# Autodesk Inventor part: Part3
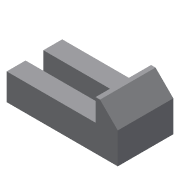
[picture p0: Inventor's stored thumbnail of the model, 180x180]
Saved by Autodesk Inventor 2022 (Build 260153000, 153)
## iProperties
Created: 2002-01
Part Number: Part3
Document SubType Name: Modeling
Designer: ***
Density: 1 g/cm^3
Material: Generic
Appearance: Default
Control State: 0
Master: False
Checked Out: False
Shininess: 77.0
Length Units: 11269
Angle Units: 11279
Time Units: 11290
Mass Units: 11283
Length Display Precision: 3
Angle Display Precision: 2
Density: 0.0
Volumn: 0.0
Area: 0.0
PropertySet Name: Model Information
Author: ***
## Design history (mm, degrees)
sketch "Sketch2"
  geometry: L1 (23.289, -5.477)-(-16.711, -5.477); L2 (-16.711, -5.477)-(-16.711, 4.523); L3 (-16.711, 4.523)-(-18.711, 4.523); L4 (-18.711, 4.523)-(-26.711, -3.477); L5 (-26.711, -3.477)-(-26.711, -17.477); L6 (-26.711, -17.477)-(23.289, -17.477); L7 (23.289, -17.477)-(23.289, -5.477)
  constraints: 14 end point, 4 parallel, 1 horizontal, 1 perpendicular
  dimensions: "d0" = 50 distance of L5.end L6.end; "d1" = 12 distance of L6.end L1.start; "d2" = 22 distance between parallel lines of L3 L6; "d3" = 135 deg angle of L5 L4; "d4" = 2 distance of L2.end L3.end; "d5" = 40 distance of L1.start L1.end
extrude "Extrusion1" new body sketch "Sketch2" stored distance "d6" = 25; taper "d7" = 0 deg
sketch "Sketch3"
  geometry: L1 (-4, -8.5)-(36, -8.5); L2 (36, -8.5)-(36, -16.5); L3 (36, -16.5)-(-4, -16.5); L4 (-4, -16.5)-(-4, -8.5); L5 (40, -25)-(40, 0) reference; L6 (40, 0)-(0, 0) reference
  constraints: 8 end point, 2 parallel, 1 horizontal, 1 perpendicular
  dimensions: "d8" = 8 distance of L1.end L2.end; "d9" = 40 distance of L1.start L1.end; "d10" = 4 distance between parallel lines of L5 L2; "d11" = 8.5 distance between parallel lines of L6 L1
extrude "Extrusion2" cut sketch "Sketch3" extent not by distance; stored distance "d12" = 25; taper "d13" = 0 deg
body "Solid1"
